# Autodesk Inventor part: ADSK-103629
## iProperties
Shininess: 0.0
Created: 2000-10
Part Number: ADSK-103629
Checked By: PT
Description: SK9032AF; Bore U=2", H3-A, c/w 1.5 HP DC Motor
Document SubType Name: Modeling
Designer: Administrator
Stock Number: ADSK-103629
Density: 1 g/cm^3
Density: 0.0
Volumn: 0.0
Area: 0.0
PropertySet Name: Model Information
Control State: 0
Master: False
Checked Out: False
Author: Administrator
